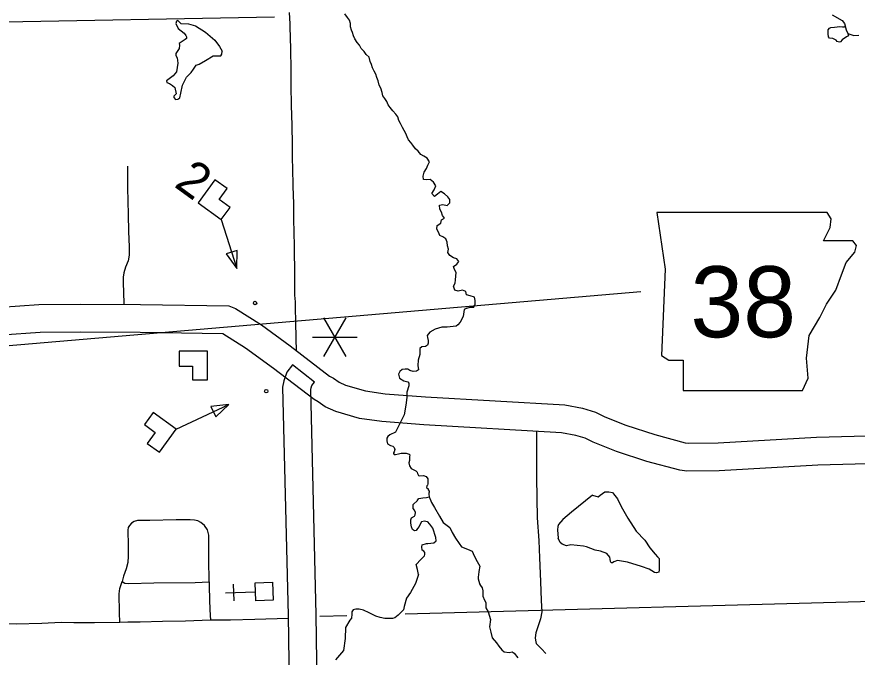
# Model space of a CAD drawing. Extents: x 1367863 to 1368197, y 380048 to 380261.
# Drawn here: x 1368043.62 to 1368072.73, y 380124.07 to 380146.25 of the extents above; entities that cross this region are included whole.
import ezdxf

# ---------------------------------------------------------------- set-up
doc = ezdxf.new("R2010")
doc.units = 0
for name, color, linetype in [('Level 10', 7, 'Continuous'), ('Level 21', 7, 'Continuous'), ('Level 31', 7, 'Continuous'), ('Level 32', 7, 'Continuous'), ('Level 35', 7, 'Continuous'), ('Level 48', 7, 'Continuous'), ('Level 5', 7, 'Continuous'), ('Level 57', 7, 'Continuous'), ('Level 58', 7, 'Continuous'), ('R_Draft', 7, 'Continuous')]:
    doc.layers.add(name, color=color, linetype=linetype)

msp = doc.modelspace()

# ---------------------------------------------------------------- linework, layer by layer
at = {"layer": 'Level 10'}
for points in [[(1368043.069, 380136.191), (1368044.388, 380136.284), (1368045.819, 380136.299), (1368047.907, 380136.279), (1368050.961, 380136.241), (1368051.199, 380136.142), (1368052.093, 380135.576), (1368053.088, 380134.849), (1368054.456, 380133.807), (1368054.59, 380133.732), (1368054.782, 380133.59), (1368055.003, 380133.496), (1368055.698, 380133.291), (1368056.375, 380133.192), (1368057.78, 380133.084), (1368062.607, 380132.808), (1368063.217, 380132.693), (1368063.665, 380132.556), (1368063.986, 380132.397), (1368064.721, 380132.102), (1368065.722, 380131.776), (1368066.776, 380131.498), (1368066.886, 380131.484), (1368067.911, 380131.495), (1368071.322, 380131.689), (1368073.931, 380131.759)], [(1368073.953, 380130.789), (1368071.363, 380130.72), (1368067.944, 380130.525), (1368066.83, 380130.513), (1368066.59, 380130.543), (1368065.448, 380130.845), (1368064.39, 380131.189), (1368063.589, 380131.511), (1368063.305, 380131.652), (1368062.985, 380131.749), (1368062.489, 380131.843), (1368057.715, 380132.116), (1368056.268, 380132.227), (1368055.489, 380132.341), (1368054.674, 380132.582), (1368054.298, 380132.742), (1368054.063, 380132.915), (1368053.921, 380132.994), (1368052.508, 380134.071), (1368051.547, 380134.773), (1368050.758, 380135.273), (1368047.896, 380135.309), (1368045.819, 380135.329), (1368044.428, 380135.314), (1368043.101, 380135.22)], [(1368053.167, 380134.193), (1368052.97, 380133.946), (1368052.872, 380133.646), (1368052.827, 380133.421), (1368053.018, 380125.515), (1368053.136, 380117.497), (1368053.105, 380115.771)], [(1368053.927, 380133.59), (1368053.167, 380134.193)], [(1368054.074, 380115.691), (1368054.107, 380117.495), (1368053.989, 380125.533), (1368053.8, 380133.337), (1368053.812, 380133.399), (1368053.838, 380133.478), (1368053.927, 380133.59)]]:
    msp.add_lwpolyline(points, dxfattribs=at)
at = {"layer": 'Level 21'}
msp.add_lwpolyline([(1368065.784, 380139.476), (1368066.08, 380137.506), (1368065.949, 380134.519), (1368066.211, 380134.355), (1368066.704, 380134.355), (1368066.704, 380133.304), (1368070.84, 380133.304), (1368071.037, 380133.731), (1368070.971, 380134.42), (1368071.07, 380135.208), (1368071.431, 380135.832), (1368071.661, 380136.292), (1368071.989, 380136.784), (1368072.186, 380137.309), (1368072.35, 380137.736), (1368072.646, 380138.097), (1368072.711, 380138.327), (1368072.58, 380138.491), (1368071.562, 380138.491), (1368071.792, 380138.951), (1368071.825, 380139.246), (1368071.689, 380139.473)], close=True, dxfattribs=at)
at = {"layer": 'Level 31'}
for points in [[(1368053.304, 380134.682), (1368053.305, 380134.725), (1368053.304, 380134.835), (1368053.302, 380134.953), (1368053.3, 380135.076), (1368053.296, 380135.204), (1368053.292, 380135.335), (1368053.289, 380135.467), (1368053.286, 380135.599), (1368053.284, 380135.729), (1368053.281, 380135.859), (1368053.278, 380135.99), (1368053.275, 380136.119), (1368053.272, 380136.249), (1368053.268, 380136.373), (1368053.266, 380136.497), (1368053.252, 380136.605), (1368053.25, 380136.751), (1368053.248, 380136.874), (1368053.246, 380137.009), (1368053.246, 380137.146), (1368053.246, 380137.284), (1368053.246, 380137.424), (1368053.246, 380137.567), (1368053.245, 380137.713), (1368053.244, 380137.863), (1368053.243, 380138.013), (1368053.242, 380138.165), (1368053.24, 380138.318), (1368053.237, 380138.472), (1368053.233, 380138.626), (1368053.227, 380138.78), (1368053.222, 380138.932), (1368053.221, 380139.086), (1368053.219, 380139.239), (1368053.218, 380139.391), (1368053.213, 380139.544), (1368053.212, 380139.696), (1368053.21, 380139.848), (1368053.207, 380140), (1368053.203, 380140.15), (1368053.198, 380140.303), (1368053.195, 380140.457), (1368053.191, 380140.613), (1368053.184, 380140.77), (1368053.18, 380140.928), (1368053.177, 380141.088), (1368053.174, 380141.25), (1368053.172, 380141.411), (1368053.17, 380141.574), (1368053.169, 380141.738), (1368053.168, 380141.904), (1368053.166, 380142.072), (1368053.163, 380142.24), (1368053.16, 380142.409), (1368053.155, 380142.58), (1368053.149, 380142.751), (1368053.144, 380142.923), (1368053.139, 380143.095), (1368053.134, 380143.267), (1368053.131, 380143.438), (1368053.128, 380143.61), (1368053.127, 380143.784), (1368053.126, 380143.959), (1368053.124, 380144.137), (1368053.123, 380144.317), (1368053.122, 380144.497), (1368053.12, 380144.678), (1368053.117, 380144.861), (1368053.114, 380145.047), (1368053.11, 380145.235), (1368053.104, 380145.425), (1368053.098, 380145.617), (1368053.092, 380145.811), (1368053.086, 380146.006), (1368053.078, 380146.203), (1368053.068, 380146.401)], [(1368050.278, 380126.677), (1368050.271, 380127.459), (1368050.271, 380128.294), (1368050.225, 380128.48), (1368050.125, 380128.626), (1368049.999, 380128.732), (1368049.887, 380128.791), (1368049.774, 380128.818), (1368049.629, 380128.824), (1368049.138, 380128.824), (1368048.231, 380128.805), (1368047.8, 380128.798), (1368047.681, 380128.765), (1368047.588, 380128.705), (1368047.522, 380128.632), (1368047.482, 380128.559), (1368047.462, 380128.467), (1368047.462, 380128.361), (1368047.476, 380128.043), (1368047.482, 380127.572), (1368047.469, 380127.353), (1368047.403, 380127.128), (1368047.317, 380126.87), (1368047.27, 380126.684)], [(1368047.184, 380125.273), (1368047.178, 380125.617), (1368047.164, 380126.267), (1368047.184, 380126.446), (1368047.27, 380126.684)], [(1368047.27, 380126.684), (1368047.356, 380126.631), (1368047.502, 380126.618), (1368048.37, 380126.638), (1368049.801, 380126.658), (1368050.278, 380126.677)], [(1368050.278, 380126.677), (1368050.278, 380126.518), (1368050.298, 380126.061), (1368050.311, 380125.71), (1368050.324, 380125.346)], [(1368047.184, 380125.273), (1368046.31, 380125.259), (1368045.594, 380125.259), (1368045.157, 380125.266), (1368044.488, 380125.233), (1368043.594, 380125.213), (1368042.998, 380125.22)], [(1368053.021, 380125.405), (1368051.861, 380125.372), (1368051.02, 380125.352), (1368050.324, 380125.346), (1368049.463, 380125.319), (1368048.661, 380125.306), (1368047.893, 380125.286), (1368047.469, 380125.286), (1368047.184, 380125.273)]]:
    msp.add_lwpolyline(points, dxfattribs=at)
at = {"layer": 'Level 32'}
for points in [[(1368047.451, 380141.079), (1368047.458, 380140.33), (1368047.473, 380139.397), (1368047.494, 380138.817), (1368047.508, 380138.287), (1368047.508, 380137.997), (1368047.473, 380137.799), (1368047.388, 380137.573), (1368047.324, 380137.382), (1368047.303, 380137.226), (1368047.303, 380137.028), (1368047.31, 380136.717), (1368047.331, 380136.302)], [(1368061.616, 380131.893), (1368061.622, 380130.819), (1368061.622, 380130.302), (1368061.635, 380129.571), (1368061.642, 380128.893), (1368061.703, 380128.114), (1368061.729, 380127.514), (1368061.763, 380126.688), (1368061.783, 380126.031), (1368061.803, 380125.635), (1368061.763, 380125.4), (1368061.602, 380124.91), (1368061.575, 380124.742), (1368061.582, 380124.654), (1368061.615, 380124.547), (1368061.797, 380124.359), (1368061.944, 380124.198)]]:
    msp.add_lwpolyline(points, dxfattribs=at)
at = {"layer": 'Level 35'}
for points in [[(1368057.271, 380141.899), (1368057.193, 380141.986), (1368057.139, 380142.095), (1368057.1, 380142.211), (1368057.038, 380142.312), (1368056.976, 380142.414), (1368056.906, 380142.553), (1368056.851, 380142.662), (1368056.813, 380142.779), (1368056.75, 380142.88), (1368056.649, 380142.996), (1368056.548, 380143.113), (1368056.479, 380143.206), (1368056.432, 380143.315), (1368056.37, 380143.416), (1368056.3, 380143.509), (1368056.277, 380143.626), (1368056.23, 380143.773), (1368056.176, 380143.882), (1368056.137, 380144.03), (1368056.09, 380144.146), (1368056.051, 380144.263), (1368055.997, 380144.372), (1368055.943, 380144.481), (1368055.911, 380144.597), (1368055.857, 380144.706), (1368055.826, 380144.854), (1368055.725, 380144.947), (1368055.655, 380145.048), (1368055.546, 380145.157), (1368055.492, 380145.265), (1368055.414, 380145.359), (1368055.329, 380145.483), (1368055.282, 380145.592), (1368055.243, 380145.708), (1368055.212, 380145.786), (1368055.181, 380145.903), (1368055.181, 380146.019), (1368055.142, 380146.136), (1368055.073, 380146.229), (1368054.979, 380146.353)], [(1368071.866, 380146.317), (1368072.209, 380146.117), (1368072.295, 380146.016), (1368072.352, 380145.802), (1368072.41, 380145.673), (1368072.61, 380145.601), (1368072.782, 380145.616)], [(1368049.198, 380146.116), (1368049.154, 380146.093), (1368049.129, 380146.017), (1368049.205, 380145.841), (1368049.414, 380145.682), (1368049.473, 380145.606), (1368049.498, 380145.556), (1368049.498, 380145.497), (1368049.448, 380145.463), (1368049.247, 380145.329), (1368049.255, 380145.262), (1368049.247, 380145.153), (1368049.129, 380144.977), (1368049.129, 380144.909), (1368049.179, 380144.834), (1368049.196, 380144.649), (1368049.154, 380144.347), (1368049.037, 380144.204), (1368048.81, 380144.036), (1368048.819, 380143.978), (1368048.911, 380143.936), (1368049.012, 380143.869), (1368049.095, 380143.801), (1368049.137, 380143.583), (1368049.062, 380143.499), (1368049.062, 380143.457), (1368049.121, 380143.39), (1368049.196, 380143.398), (1368049.272, 380143.44), (1368049.305, 380143.608), (1368049.364, 380143.877), (1368049.498, 380144.154), (1368049.658, 380144.322), (1368049.742, 380144.439), (1368049.834, 380144.574), (1368049.935, 380144.607), (1368050.161, 380144.733), (1368050.421, 380144.893), (1368050.547, 380144.893), (1368050.69, 380144.893), (1368050.723, 380144.951), (1368050.735, 380145.055)], [(1368049.198, 380146.116), (1368049.306, 380146.023), (1368049.567, 380146.008), (1368049.813, 380145.931), (1368050.151, 380145.716), (1368050.474, 380145.439), (1368050.643, 380145.224), (1368050.735, 380145.055)], [(1368072.41, 380145.673), (1368072.431, 380145.595), (1368072.354, 380145.561), (1368072.208, 380145.449), (1368072.155, 380145.38), (1368072.155, 380145.38), (1368072.112, 380145.376), (1368072.036, 380145.399), (1368072.001, 380145.442), (1368071.89, 380145.495), (1368071.775, 380145.507), (1368071.736, 380145.553), (1368071.725, 380145.657), (1368071.721, 380145.803), (1368071.767, 380145.86), (1368071.813, 380145.883), (1368071.947, 380145.891), (1368072.124, 380145.91), (1368072.22, 380145.906), (1368072.274, 380145.906), (1368072.319, 380145.927)], [(1368058.268, 380139.59), (1368058.257, 380139.723), (1368058.374, 380139.747), (1368058.522, 380139.708), (1368058.615, 380139.801), (1368058.615, 380139.918), (1368058.553, 380140.019), (1368058.436, 380140.12), (1368058.312, 380140.197), (1368058.195, 380140.104), (1368058.094, 380140.026), (1368058.001, 380140.127), (1368058.079, 380140.252), (1368058.133, 380140.392), (1368058.055, 380140.524), (1368057.939, 380140.617), (1368057.822, 380140.601), (1368057.706, 380140.617), (1368057.69, 380140.733), (1368057.729, 380140.873), (1368057.807, 380140.998), (1368057.853, 380141.106), (1368057.916, 380141.231), (1368057.83, 380141.355), (1368057.721, 380141.417), (1368057.62, 380141.479), (1368057.519, 380141.596), (1368057.434, 380141.682), (1368057.333, 380141.798), (1368057.271, 380141.899)], [(1368059.206, 380136.157), (1368059.32, 380136.195), (1368059.445, 380136.19), (1368059.502, 380136.299), (1368059.502, 380136.423), (1368059.471, 380136.537), (1368059.326, 380136.589), (1368059.201, 380136.615), (1368059.175, 380136.734), (1368059.061, 380136.776), (1368058.911, 380136.745), (1368058.797, 380136.786), (1368058.745, 380136.921), (1368058.807, 380137.019), (1368058.812, 380137.144), (1368058.828, 380137.263), (1368058.838, 380137.387), (1368058.776, 380137.491), (1368058.75, 380137.605), (1368058.859, 380137.678), (1368058.932, 380137.771), (1368058.859, 380137.864), (1368058.745, 380137.9), (1368058.615, 380137.978), (1368058.553, 380138.082), (1368058.569, 380138.201), (1368058.538, 380138.32), (1368058.522, 380138.445), (1368058.481, 380138.564), (1368058.382, 380138.626), (1368058.273, 380138.678), (1368058.227, 380138.787), (1368058.165, 380138.896), (1368058.18, 380139.015), (1368058.31, 380139.098), (1368058.325, 380139.222), (1368058.434, 380139.269), (1368058.367, 380139.367), (1368058.325, 380139.481), (1368058.268, 380139.59)], [(1368059.206, 380136.157), (1368059.113, 380136.106), (1368059.079, 380135.868), (1368058.977, 380135.672), (1368058.901, 380135.579), (1368058.841, 380135.537), (1368058.731, 380135.52), (1368058.527, 380135.503), (1368058.34, 380135.494), (1368058.111, 380135.426), (1368057.924, 380135.324), (1368057.839, 380135.214), (1368057.847, 380135.137), (1368057.864, 380135.035), (1368057.864, 380134.942), (1368057.847, 380134.874), (1368057.78, 380134.831), (1368057.644, 380134.823), (1368057.584, 380134.755), (1368057.576, 380134.695), (1368057.576, 380134.551), (1368057.525, 380134.356), (1368057.508, 380134.177), (1368057.533, 380134.024), (1368057.465, 380133.973), (1368057.346, 380133.965), (1368057.236, 380133.999), (1368057.16, 380134.041), (1368057.075, 380134.041), (1368056.973, 380134.033), (1368056.888, 380133.965), (1368056.845, 380133.871), (1368056.871, 380133.735), (1368057.024, 380133.642), (1368057.16, 380133.608), (1368057.194, 380133.557), (1368057.194, 380133.463), (1368057.126, 380133.243), (1368057.126, 380133.064), (1368057.092, 380132.792), (1368057.032, 380132.461), (1368056.922, 380132.232), (1368056.735, 380131.866), (1368056.541, 380131.77), (1368056.473, 380131.711), (1368056.442, 380131.655), (1368056.433, 380131.559), (1368056.464, 380131.461), (1368056.569, 380131.399), (1368056.649, 380131.374), (1368056.686, 380131.334), (1368056.714, 380131.266), (1368056.686, 380131.186), (1368056.671, 380131.145), (1368056.668, 380131.118), (1368056.689, 380131.09), (1368056.742, 380131.09), (1368056.841, 380131.114), (1368056.936, 380131.136), (1368057.011, 380131.136), (1368057.112, 380131.13), (1368057.214, 380131.105), (1368057.23, 380131.08), (1368057.224, 380131.006), (1368057.217, 380130.886), (1368057.199, 380130.799), (1368057.227, 380130.694), (1368057.279, 380130.608), (1368057.369, 380130.555), (1368057.44, 380130.524), (1368057.489, 380130.481), (1368057.502, 380130.425), (1368057.529, 380130.357), (1368057.566, 380130.345), (1368057.705, 380130.364), (1368057.801, 380130.33), (1368057.86, 380130.243), (1368057.86, 380130.194), (1368057.86, 380130.12), (1368057.857, 380130.067), (1368057.841, 380130.03), (1368057.823, 380130.002), (1368057.814, 380129.95), (1368057.866, 380129.894), (1368057.872, 380129.866), (1368057.909, 380129.82), (1368057.906, 380129.78), (1368057.894, 380129.746), (1368057.888, 380129.712), (1368057.904, 380129.623)], [(1368057.535, 380126.937), (1368057.494, 380127.103), (1368057.455, 380127.283), (1368057.616, 380127.456), (1368057.699, 380127.527), (1368057.744, 380127.584), (1368057.757, 380127.629), (1368057.757, 380127.7), (1368057.718, 380127.738), (1368057.66, 380127.77), (1368057.648, 380127.886), (1368057.66, 380127.956), (1368057.814, 380128.001), (1368057.859, 380128.007), (1368058.064, 380128.033), (1368058.141, 380128.104), (1368058.135, 380128.219), (1368058.032, 380128.54), (1368057.93, 380128.674), (1368057.846, 380128.77), (1368057.834, 380128.758), (1368057.744, 380128.777), (1368057.635, 380128.751), (1368057.59, 380128.681), (1368057.552, 380128.597), (1368057.494, 380128.527), (1368057.449, 380128.456), (1368057.391, 380128.45), (1368057.321, 380128.488), (1368057.289, 380128.584), (1368057.27, 380128.706), (1368057.27, 380128.822), (1368057.295, 380128.899), (1368057.398, 380128.956), (1368057.423, 380129.001), (1368057.43, 380129.078), (1368057.398, 380129.155), (1368057.353, 380129.213), (1368057.353, 380129.347), (1368057.353, 380129.36), (1368057.494, 380129.495), (1368057.5, 380129.508), (1368057.545, 380129.559), (1368057.68, 380129.585), (1368057.814, 380129.597), (1368057.904, 380129.623)], [(1368057.904, 380129.623), (1368057.962, 380129.482), (1368057.987, 380129.424), (1368058.09, 380129.258), (1368058.257, 380128.956), (1368058.385, 380128.732), (1368058.615, 380128.565), (1368058.699, 380128.386), (1368058.82, 380128.193), (1368058.942, 380128.007), (1368059.026, 380127.892), (1368059.231, 380127.809), (1368059.397, 380127.745), (1368059.461, 380127.584), (1368059.57, 380127.379), (1368059.654, 380127.219), (1368059.626, 380127.035), (1368059.613, 380126.92), (1368059.6, 380126.849), (1368059.6, 380126.779), (1368059.645, 380126.625), (1368059.645, 380126.612), (1368059.684, 380126.555), (1368059.741, 380126.465), (1368059.761, 380126.369), (1368059.761, 380126.285), (1368059.761, 380126.183), (1368059.818, 380126.042), (1368059.87, 380125.958), (1368059.87, 380125.837), (1368059.87, 380125.772), (1368059.947, 380125.638), (1368060.023, 380125.368), (1368059.998, 380125.125), (1368060.017, 380125.029), (1368060.036, 380124.933), (1368060.088, 380124.74), (1368060.235, 380124.567), (1368060.318, 380124.445), (1368060.421, 380124.323), (1368060.504, 380124.253), (1368060.677, 380124.227), (1368060.773, 380124.255), (1368060.85, 380124.21), (1368060.972, 380124.05)], [(1368063.557, 380129.676), (1368062.835, 380129.096), (1368062.531, 380128.84), (1368062.379, 380128.669), (1368062.36, 380128.593), (1368062.351, 380128.479), (1368062.37, 380128.194)], [(1368063.557, 380129.676), (1368063.757, 380129.619), (1368063.823, 380129.676), (1368063.985, 380129.79), (1368064.127, 380129.8), (1368064.251, 380129.771), (1368064.289, 380129.724), (1368064.431, 380129.553), (1368064.555, 380129.287), (1368064.783, 380128.878), (1368065.077, 380128.431), (1368065.372, 380128.127), (1368065.543, 380127.861), (1368065.733, 380127.633), (1368065.809, 380127.547), (1368065.866, 380127.49), (1368065.866, 380127.386), (1368065.866, 380127.262), (1368065.875, 380127.186), (1368065.875, 380127.091), (1368065.856, 380127.015), (1368065.78, 380126.987), (1368065.714, 380126.996), (1368065.524, 380127.12), (1368065.258, 380127.215), (1368064.773, 380127.357), (1368064.422, 380127.414), (1368064.298, 380127.376), (1368064.251, 380127.338), (1368064.203, 380127.338), (1368064.184, 380127.386), (1368064.175, 380127.462), (1368064.165, 380127.538), (1368064.061, 380127.661), (1368063.842, 380127.737), (1368063.652, 380127.775), (1368063.358, 380127.889), (1368063.244, 380127.908), (1368062.816, 380127.956), (1368062.664, 380127.928), (1368062.512, 380127.985), (1368062.446, 380128.042), (1368062.37, 380128.194)], [(1368057.535, 380126.937), (1368057.428, 380126.615), (1368057.257, 380126.314), (1368057.117, 380126.111), (1368057.042, 380125.821), (1368057.01, 380125.703), (1368056.828, 380125.521), (1368056.72, 380125.435), (1368056.635, 380125.413), (1368056.517, 380125.403), (1368056.366, 380125.403), (1368056.206, 380125.445), (1368056.056, 380125.488), (1368055.82, 380125.606), (1368055.627, 380125.692), (1368055.476, 380125.735), (1368055.369, 380125.735), (1368055.273, 380125.703), (1368055.23, 380125.639), (1368055.23, 380125.563), (1368055.219, 380125.424), (1368055.155, 380125.349), (1368055.005, 380125.091), (1368054.994, 380124.715), (1368054.939, 380124.303), (1368054.664, 380123.974)]]:
    msp.add_lwpolyline(points, dxfattribs=at)
at = {"layer": 'Level 48'}
for p, q in [((1368055.021, 380135.823), (1368054.245, 380134.479)), ((1368054.245, 380135.823), (1368055.021, 380134.479)), ((1368053.857, 380135.151), (1368055.409, 380135.151))]:
    msp.add_line(p, q, dxfattribs=at)
at = {"layer": 'Level 5'}
for points in [[(1368052.541, 380146.238), (1368032.607, 380145.868)], [(1368057.075, 380125.565), (1368074.125, 380126.034)], [(1368054.114, 380125.484), (1368055.047, 380125.509)]]:
    msp.add_lwpolyline(points, dxfattribs=at)
at = {"layer": 'Level 57'}
for p, q in [((1368051.145, 380126.017), (1368051.124, 380126.599)), ((1368050.844, 380126.298), (1368051.888, 380126.335))]:
    msp.add_line(p, q, dxfattribs=at)
msp.add_lwpolyline([(1368052.505, 380126.041), (1368051.899, 380126.02), (1368051.877, 380126.648), (1368052.482, 380126.669)], close=True, dxfattribs=at)
at = {"layer": 'Level 58'}
for points in [[(1368049.902, 380139.806), (1368050.699, 380139.226), (1368051.005, 380139.646), (1368050.627, 380139.921), (1368050.901, 380140.297), (1368050.481, 380140.603)], [(1368051.249, 380138.157), (1368050.872, 380138.036), (1368051.241, 380137.531)], [(1368050.227, 380134.665), (1368049.241, 380134.665), (1368049.241, 380134.145), (1368049.708, 380134.145), (1368049.708, 380133.679), (1368050.227, 380133.679)], [(1368050.339, 380132.75), (1368050.509, 380132.392), (1368050.96, 380132.826)], [(1368049.142, 380131.962), (1368048.346, 380132.544), (1368048.04, 380132.124), (1368048.416, 380131.849), (1368048.141, 380131.473), (1368048.561, 380131.166)]]:
    msp.add_lwpolyline(points, close=True, dxfattribs=at)
for points in [[(1368050.699, 380139.226), (1368051.241, 380137.531)], [(1368049.142, 380131.962), (1368050.96, 380132.826)]]:
    msp.add_lwpolyline(points, dxfattribs=at)
for centre in [(1368051.873, 380136.336), (1368052.26, 380133.282)]:
    msp.add_circle(centre, 0.0582, dxfattribs=at)
at = {"layer": 'R_Draft'}
msp.add_lwpolyline([(1368031.989, 380133.895), (1368065.24, 380136.731)], dxfattribs=at)

# ---------------------------------------------------------------- texts
at = {"layer": 'Level 21'}
msp.add_text('38', height=2.459, dxfattribs=at).set_placement((1368066.953, 380135.15))
at = {"layer": 'Level 58'}
msp.add_text('2', height=1.23, rotation=323.963, dxfattribs=at).set_placement((1368049.032, 380140.391))

doc.saveas('drawing.dxf')
